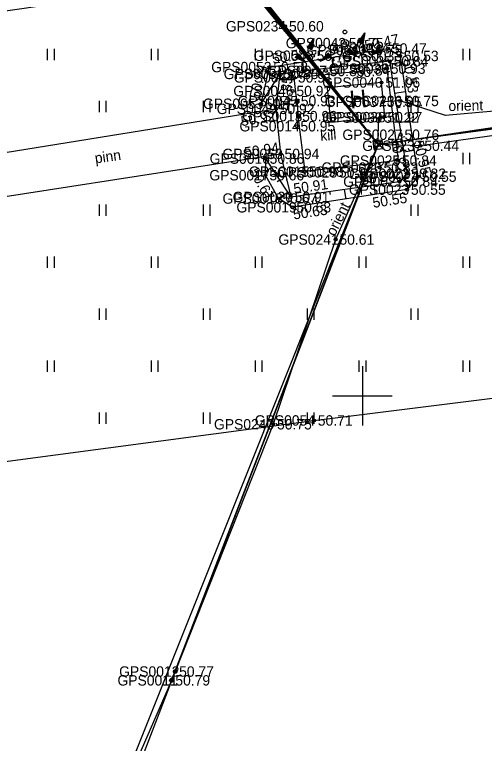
# Model space of a CAD drawing. Extents: x 563121 to 567545, y 6570841 to 6581299.
# Drawn here: x 565876.57 to 565908.23, y 6571676.57 to 6571725.69 of the extents above; entities that cross this region are included whole.
import ezdxf

# ---------------------------------------------------------------- set-up
doc = ezdxf.new("R2010")
doc.units = 0
for name, color, linetype in [('AED', 7, 'Continuous'), ('HALJASTUS', 7, 'Continuous'), ('HOONE', 7, 'Continuous'), ('KORGUS-EH2000', 7, 'Continuous'), ('MOOTKORG-EH2000', 7, 'Continuous'), ('MOOTMPUNKT', 7, 'Continuous'), ('MOOTNR', 7, 'Continuous'), ('MOOTPIIR', 7, 'Continuous'), ('MPKAABEL', 7, 'Continuous'), ('POST', 7, 'Continuous'), ('PUU', 7, 'Continuous'), ('RAJATIS', 7, 'Continuous'), ('RELJEEF', 7, 'Continuous'), ('SIOHULIIN', 7, 'Continuous'), ('TEE', 7, 'Continuous'), ('VORK', 7, 'Continuous')]:
    doc.layers.add(name, color=color, linetype=linetype)

msp = doc.modelspace()

# ---------------------------------------------------------------- linework, layer by layer
at = {"layer": 'AED'}
for p, q in [((565895.47, 6571719.988), (565895.47, 6571719.738)), ((565895.47, 6571719.988), (565895.72, 6571719.988)), ((565895.595, 6571719.863), (565895.684, 6571718.847)), ((565895.72, 6571719.988), (565895.72, 6571719.738)), ((565895.47, 6571719.738), (565895.72, 6571719.738)), ((565895.559, 6571718.972), (565895.559, 6571718.722)), ((565895.559, 6571718.972), (565895.809, 6571718.972)), ((565895.809, 6571718.972), (565895.809, 6571718.722)), ((565895.559, 6571718.722), (565895.809, 6571718.722))]:
    msp.add_line(p, q, dxfattribs=at)
msp.add_lwpolyline([(565895.595, 6571719.863), (565895.398, 6571721.461), (565901.655, 6571722.049), (565902.407, 6571715.849), (565896.139, 6571715.109), (565895.684, 6571718.847)], dxfattribs=at)
at = {"layer": 'HALJASTUS'}
for p, q in [((565878.772, 6571723.381), (565878.772, 6571722.619)), ((565879.228, 6571723.381), (565879.228, 6571722.619)), ((565885.772, 6571723.381), (565885.772, 6571722.619)), ((565886.228, 6571723.381), (565886.228, 6571722.619)), ((565892.772, 6571723.381), (565892.772, 6571722.619)), ((565893.228, 6571723.381), (565893.228, 6571722.619)), ((565906.772, 6571723.381), (565906.772, 6571722.619)), ((565907.228, 6571723.381), (565907.228, 6571722.619)), ((565882.272, 6571719.881), (565882.272, 6571719.119)), ((565882.728, 6571719.881), (565882.728, 6571719.119)), ((565889.272, 6571719.881), (565889.272, 6571719.119)), ((565889.728, 6571719.881), (565889.728, 6571719.119)), ((565903.272, 6571719.881), (565903.272, 6571719.119)), ((565903.728, 6571719.881), (565903.728, 6571719.119)), ((565906.772, 6571716.381), (565906.772, 6571715.619)), ((565907.228, 6571716.381), (565907.228, 6571715.619)), ((565882.272, 6571712.881), (565882.272, 6571712.119)), ((565882.728, 6571712.881), (565882.728, 6571712.119)), ((565889.272, 6571712.881), (565889.272, 6571712.119)), ((565889.728, 6571712.881), (565889.728, 6571712.119)), ((565903.272, 6571712.881), (565903.272, 6571712.119)), ((565903.728, 6571712.881), (565903.728, 6571712.119)), ((565878.772, 6571709.381), (565878.772, 6571708.619)), ((565879.228, 6571709.381), (565879.228, 6571708.619)), ((565885.772, 6571709.381), (565885.772, 6571708.619)), ((565886.228, 6571709.381), (565886.228, 6571708.619)), ((565892.772, 6571709.381), (565892.772, 6571708.619)), ((565893.228, 6571709.381), (565893.228, 6571708.619)), ((565899.772, 6571709.381), (565899.772, 6571708.619)), ((565900.228, 6571709.381), (565900.228, 6571708.619)), ((565906.772, 6571709.381), (565906.772, 6571708.619)), ((565907.228, 6571709.381), (565907.228, 6571708.619)), ((565882.272, 6571705.881), (565882.272, 6571705.119)), ((565882.728, 6571705.881), (565882.728, 6571705.119)), ((565889.272, 6571705.881), (565889.272, 6571705.119)), ((565889.728, 6571705.881), (565889.728, 6571705.119)), ((565896.272, 6571705.881), (565896.272, 6571705.119)), ((565896.728, 6571705.881), (565896.728, 6571705.119)), ((565903.272, 6571705.881), (565903.272, 6571705.119)), ((565903.728, 6571705.881), (565903.728, 6571705.119)), ((565878.772, 6571702.381), (565878.772, 6571701.619)), ((565879.228, 6571702.381), (565879.228, 6571701.619)), ((565885.772, 6571702.381), (565885.772, 6571701.619)), ((565886.228, 6571702.381), (565886.228, 6571701.619)), ((565892.772, 6571702.381), (565892.772, 6571701.619)), ((565893.228, 6571702.381), (565893.228, 6571701.619)), ((565899.772, 6571702.381), (565899.772, 6571701.619)), ((565900.228, 6571702.381), (565900.228, 6571701.619)), ((565906.772, 6571702.381), (565906.772, 6571701.619)), ((565907.228, 6571702.381), (565907.228, 6571701.619)), ((565882.272, 6571698.881), (565882.272, 6571698.119)), ((565882.728, 6571698.881), (565882.728, 6571698.119)), ((565889.272, 6571698.881), (565889.272, 6571698.119)), ((565889.728, 6571698.881), (565889.728, 6571698.119)), ((565896.272, 6571698.881), (565896.272, 6571698.119)), ((565896.728, 6571698.881), (565896.728, 6571698.119))]:
    msp.add_line(p, q, dxfattribs=at)
at = {"layer": 'KORGUS-EH2000'}
for centre in [(565901.738, 6571723.406), (565902.538, 6571722.902), (565901.848, 6571722.544), (565893.739, 6571722.155), (565894.437, 6571721.691), (565893.18, 6571719.681), (565894.174, 6571719.336), (565894.496, 6571716.301), (565903.034, 6571714.964), (565902.49, 6571714.435), (565903.744, 6571714.768), (565903.014, 6571713.894), (565895.181, 6571713.4), (565894.357, 6571713.294), (565895.296, 6571712.704), (565898.197, 6571710.531), (565896.74, 6571698.337)]:
    msp.add_circle(centre, 0.1, dxfattribs=at)
at = {"layer": 'MOOTMPUNKT'}
for centre in [(565894.796, 6571724.904), (565898.828, 6571723.769), (565900.099, 6571723.304), (565901.738, 6571723.406), (565896.666, 6571722.92), (565902.538, 6571722.902), (565901.848, 6571722.544), (565893.739, 6571722.155), (565894.437, 6571721.691), (565897.546, 6571721.893), (565901.655, 6571722.049), (565895.398, 6571721.461), (565901.292, 6571721.115), (565895.298, 6571720.541), (565895.595, 6571719.863), (565901.383, 6571719.81), (565902.551, 6571719.869), (565893.18, 6571719.681), (565894.174, 6571719.336), (565895.684, 6571718.847), (565901.218, 6571718.748), (565901.435, 6571718.779), (565895.569, 6571718.167), (565902.576, 6571717.595), (565903.915, 6571716.853), (565894.496, 6571716.301), (565893.493, 6571715.986), (565902.407, 6571715.849), (565901.169, 6571715.383), (565893.476, 6571714.867), (565896.139, 6571715.109), (565898.167, 6571715.059), (565903.034, 6571714.964), (565902.49, 6571714.435), (565903.744, 6571714.768), (565903.014, 6571713.894), (565895.181, 6571713.4), (565894.357, 6571713.294), (565895.296, 6571712.704), (565898.197, 6571710.531), (565896.74, 6571698.337), (565893.993, 6571698.08), (565887.395, 6571681.416), (565887.141, 6571680.821)]:
    msp.add_circle(centre, 0.1, dxfattribs=at)
at = {"layer": 'MOOTPIIR'}
msp.add_lwpolyline([(565847.666, 6571692.22), (565872.552, 6571695.122), (565896.74, 6571698.337), (565923.667, 6571701.7), (565921.225, 6571716.927), (565918.14, 6571731.716), (565901.33, 6571729.772), (565893.791, 6571728.537), (565867.263, 6571724.668), (565843.294, 6571721.486)], dxfattribs=at)
at = {"layer": 'MPKAABEL'}
for points in [[(565868.038, 6571758.236), (565867.453, 6571757.822), (565877.123, 6571746.517), (565877.646, 6571745.913), (565888.681, 6571732.586), (565894.796, 6571724.904), (565901.066, 6571716.93)], [(565953.537, 6571723.916), (565953.549, 6571724.752), (565939.474, 6571722.251), (565938.668, 6571722.15), (565916.898, 6571718.657), (565903.915, 6571716.853), (565901.066, 6571716.93)], [(565921.258, 6571720.287), (565905.596, 6571718.882), (565902.551, 6571719.869), (565901.417, 6571719.812)], [(565901.066, 6571716.93), (565898.197, 6571710.531), (565893.993, 6571698.08), (565887.395, 6571681.416), (565887.141, 6571680.821), (565881.237, 6571667.241), (565881.853, 6571666.983)]]:
    msp.add_lwpolyline(points, dxfattribs=at)
at = {"layer": 'POST'}
for p, q in [((565900.739, 6571717.2), (565901.336, 6571717.257)), ((565901.394, 6571716.66), (565900.739, 6571717.2)), ((565900.796, 6571716.603), (565900.739, 6571717.2)), ((565901.336, 6571717.257), (565900.796, 6571716.603)), ((565901.394, 6571716.66), (565901.336, 6571717.257)), ((565900.796, 6571716.603), (565901.394, 6571716.66))]:
    msp.add_line(p, q, dxfattribs=at)
for points in [[(565868.038, 6571758.236), (565901.066, 6571716.93), (565867.453, 6571757.822)], [(565877.123, 6571746.517), (565901.066, 6571716.93), (565877.646, 6571745.913)], [(565953.537, 6571723.916), (565901.066, 6571716.93), (565953.549, 6571724.752)], [(565939.474, 6571722.251), (565901.066, 6571716.93), (565938.668, 6571722.15)], [(565881.853, 6571666.983), (565901.066, 6571716.93), (565881.237, 6571667.241)], [(565887.141, 6571680.821), (565901.066, 6571716.93), (565887.395, 6571681.416)]]:
    msp.add_lwpolyline(points, dxfattribs=at)
for centre, radius in [((565887.395, 6571681.416), 0.125), ((565887.395, 6571681.416), 0.105), ((565887.395, 6571681.416), 0.0851), ((565887.395, 6571681.416), 0.0651), ((565887.395, 6571681.416), 0.0451), ((565887.395, 6571681.416), 0.0251), ((565887.395, 6571681.416), 0.00511), ((565887.141, 6571680.821), 0.125), ((565887.141, 6571680.821), 0.105), ((565887.141, 6571680.821), 0.0851), ((565887.141, 6571680.821), 0.0651), ((565887.141, 6571680.821), 0.0451), ((565887.141, 6571680.821), 0.0251), ((565887.141, 6571680.821), 0.00511)]:
    msp.add_circle(centre, radius, dxfattribs=at)
at = {"layer": 'PUU'}
for centre, radius in [((565898.828, 6571724.519), 0.125), ((565898.828, 6571723.769), 0.25), ((565898.178, 6571723.394), 0.125), ((565899.478, 6571723.394), 0.125)]:
    msp.add_circle(centre, radius, dxfattribs=at)
at = {"layer": 'RAJATIS'}
msp.add_lwpolyline([(565901.292, 6571721.115), (565897.637, 6571720.765), (565897.859, 6571718.445), (565901.514, 6571718.795)], close=True, dxfattribs=at)
at = {"layer": 'RELJEEF'}
for p, q in [((565899.744, 6571723.83), (565900.164, 6571724.47)), ((565899.994, 6571724.205), (565900.124, 6571724.265)), ((565900.164, 6571724.47), (565900.024, 6571723.715)), ((565900.039, 6571724.28), (565900.139, 6571724.32)), ((565900.089, 6571724.355), (565900.149, 6571724.38)), ((565900.139, 6571724.43), (565900.159, 6571724.44)), ((565896.311, 6571723.446), (565896.731, 6571724.086)), ((565896.511, 6571723.746), (565896.681, 6571723.821)), ((565896.561, 6571723.821), (565896.691, 6571723.881)), ((565896.586, 6571723.726), (565896.671, 6571723.761)), ((565896.731, 6571724.086), (565896.591, 6571723.331)), ((565896.606, 6571723.896), (565896.706, 6571723.936)), ((565896.656, 6571723.971), (565896.716, 6571723.996)), ((565896.706, 6571724.046), (565896.726, 6571724.056)), ((565899.744, 6571723.83), (565900.069, 6571723.97)), ((565899.744, 6571723.83), (565900.024, 6571723.715)), ((565899.744, 6571723.83), (565899.744, 6571723.83)), ((565899.794, 6571723.905), (565900.079, 6571724.025)), ((565899.809, 6571723.805), (565900.059, 6571723.91)), ((565899.844, 6571723.98), (565900.094, 6571724.085)), ((565899.874, 6571723.775), (565900.049, 6571723.85)), ((565899.894, 6571724.055), (565900.019, 6571724.11)), ((565899.944, 6571724.13), (565900.114, 6571724.205)), ((565899.944, 6571723.75), (565900.039, 6571723.79)), ((565900.019, 6571724.11), (565900.104, 6571724.145)), ((565896.311, 6571723.446), (565896.636, 6571723.586)), ((565896.311, 6571723.446), (565896.591, 6571723.331)), ((565896.311, 6571723.446), (565896.311, 6571723.446)), ((565896.361, 6571723.521), (565896.646, 6571723.641)), ((565896.376, 6571723.421), (565896.626, 6571723.526)), ((565896.411, 6571723.596), (565896.661, 6571723.701)), ((565896.441, 6571723.391), (565896.616, 6571723.466)), ((565896.461, 6571723.671), (565896.586, 6571723.726)), ((565896.511, 6571723.366), (565896.606, 6571723.406)), ((565896.576, 6571723.341), (565896.591, 6571723.346)), ((565899.103, 6571723.429), (565898.918, 6571723.189)), ((565898.973, 6571723.259), (565898.988, 6571723.159)), ((565899.018, 6571723.319), (565899.043, 6571723.134)), ((565899.058, 6571723.374), (565899.093, 6571723.104)), ((565899.103, 6571723.429), (565899.608, 6571722.859)), ((565899.103, 6571723.429), (565899.148, 6571723.079)), ((565899.103, 6571723.429), (565899.103, 6571723.429)), ((565899.163, 6571723.364), (565899.203, 6571723.054)), ((565899.223, 6571723.294), (565899.258, 6571723.029)), ((565900.009, 6571723.725), (565900.024, 6571723.73)), ((565900.582, 6571722.924), (565901.122, 6571723.469)), ((565901.207, 6571723.184), (565900.902, 6571723.244)), ((565901.292, 6571723.219), (565900.942, 6571723.284)), ((565901.252, 6571723.274), (565900.987, 6571723.329)), ((565901.212, 6571723.334), (565901.027, 6571723.369)), ((565901.172, 6571723.394), (565901.072, 6571723.414)), ((565901.132, 6571723.454), (565901.112, 6571723.454)), ((565901.292, 6571723.219), (565901.122, 6571723.469)), ((565895.669, 6571723.045), (565895.484, 6571722.805)), ((565896.174, 6571722.475), (565895.484, 6571722.805)), ((565895.494, 6571722.82), (565895.499, 6571722.8)), ((565895.539, 6571722.875), (565895.554, 6571722.775)), ((565895.584, 6571722.935), (565895.609, 6571722.75)), ((565895.624, 6571722.99), (565895.659, 6571722.72)), ((565895.669, 6571723.045), (565896.174, 6571722.475)), ((565895.669, 6571723.045), (565895.714, 6571722.695)), ((565895.669, 6571723.045), (565895.669, 6571723.045)), ((565895.729, 6571722.98), (565895.769, 6571722.67)), ((565895.789, 6571722.91), (565895.824, 6571722.645)), ((565895.849, 6571722.845), (565895.864, 6571722.705)), ((565895.904, 6571722.775), (565895.934, 6571722.59)), ((565897.149, 6571722.54), (565897.689, 6571723.085)), ((565897.859, 6571722.835), (565897.149, 6571722.54)), ((565897.474, 6571722.755), (565897.384, 6571722.775)), ((565897.689, 6571722.765), (565897.424, 6571722.815)), ((565897.774, 6571722.8), (565897.469, 6571722.86)), ((565897.609, 6571722.73), (565897.474, 6571722.755)), ((565897.859, 6571722.835), (565897.509, 6571722.9)), ((565897.819, 6571722.89), (565897.554, 6571722.945)), ((565897.779, 6571722.95), (565897.594, 6571722.985)), ((565897.739, 6571723.01), (565897.639, 6571723.03)), ((565897.699, 6571723.07), (565897.679, 6571723.07)), ((565897.859, 6571722.835), (565897.689, 6571723.085)), ((565897.859, 6571722.835), (565897.859, 6571722.835)), ((565898.043, 6571722.106), (565897.961, 6571722.815)), ((565899.608, 6571722.859), (565898.918, 6571723.189)), ((565898.928, 6571723.204), (565898.933, 6571723.184)), ((565899.283, 6571723.229), (565899.298, 6571723.089)), ((565899.298, 6571723.089), (565899.313, 6571722.999)), ((565899.338, 6571723.159), (565899.368, 6571722.974)), ((565899.398, 6571723.094), (565899.418, 6571722.949)), ((565899.458, 6571723.024), (565899.473, 6571722.924)), ((565899.518, 6571722.959), (565899.528, 6571722.894)), ((565899.578, 6571722.889), (565899.583, 6571722.869)), ((565900.03, 6571722.334), (565899.939, 6571723.124)), ((565901.292, 6571723.219), (565900.582, 6571722.924)), ((565900.622, 6571722.939), (565900.607, 6571722.944)), ((565900.707, 6571722.974), (565900.647, 6571722.989)), ((565900.792, 6571723.009), (565900.687, 6571723.029)), ((565900.872, 6571723.044), (565900.732, 6571723.074)), ((565900.957, 6571723.079), (565900.772, 6571723.114)), ((565900.907, 6571723.139), (565900.817, 6571723.159)), ((565901.122, 6571723.149), (565900.857, 6571723.199)), ((565901.042, 6571723.114), (565900.907, 6571723.139)), ((565901.292, 6571723.219), (565901.292, 6571723.219)), ((565895.864, 6571722.705), (565895.879, 6571722.615)), ((565895.964, 6571722.71), (565895.984, 6571722.565)), ((565896.056, 6571721.877), (565895.984, 6571722.506)), ((565896.024, 6571722.64), (565896.039, 6571722.54)), ((565896.084, 6571722.575), (565896.094, 6571722.51)), ((565896.144, 6571722.505), (565896.149, 6571722.485)), ((565897.189, 6571722.555), (565897.174, 6571722.56)), ((565897.274, 6571722.59), (565897.214, 6571722.605)), ((565897.359, 6571722.625), (565897.254, 6571722.645)), ((565897.439, 6571722.66), (565897.299, 6571722.69)), ((565897.524, 6571722.695), (565897.339, 6571722.73)), ((565899.036, 6571722.22), (565899.011, 6571722.445)), ((565901.023, 6571722.449), (565900.995, 6571722.698)), ((565901.874, 6571722.376), (565902.599, 6571722.489)), ((565895.063, 6571721.763), (565895.042, 6571721.939)), ((565897.05, 6571721.991), (565897.027, 6571722.192)), ((565894.241, 6571721.377), (565893.647, 6571721.748)), ((565902.029, 6571721.388), (565902.244, 6571721.421)), ((565893.711, 6571720.529), (565893.622, 6571720.585)), ((565902.183, 6571720.4), (565902.892, 6571720.511)), ((565902.338, 6571719.412), (565902.548, 6571719.445)), ((565902.492, 6571718.424), (565903.186, 6571718.532)), ((565902.647, 6571717.436), (565902.853, 6571717.468)), ((565902.802, 6571716.448), (565903.479, 6571716.554)), ((565902.956, 6571715.46), (565903.157, 6571715.491)), ((565893.892, 6571715.375), (565893.48, 6571715.105)), ((565894.439, 6571714.537), (565894.268, 6571714.426)), ((565902.677, 6571714.617), (565903.183, 6571714.096)), ((565898.787, 6571713.911), (565898.88, 6571713.257)), ((565899.778, 6571714.051), (565899.805, 6571713.858)), ((565900.768, 6571714.191), (565900.857, 6571713.562)), ((565901.758, 6571714.331), (565901.784, 6571714.146)), ((565894.986, 6571713.7), (565894.361, 6571713.292)), ((565895.817, 6571713.49), (565895.846, 6571713.283)), ((565896.807, 6571713.63), (565896.903, 6571712.952)), ((565897.797, 6571713.77), (565897.826, 6571713.571))]:
    msp.add_line(p, q, dxfattribs=at)
for points in [[(565893.18, 6571719.681), (565893.739, 6571722.155), (565901.738, 6571723.406), (565902.538, 6571722.902), (565903.744, 6571714.768), (565903.014, 6571713.894), (565895.296, 6571712.704), (565894.357, 6571713.294), (565893.476, 6571714.867), (565893.493, 6571715.986)], [(565893.18, 6571719.681), (565894.437, 6571721.691)], [(565895.181, 6571713.4), (565893.493, 6571715.986)]]:
    msp.add_lwpolyline(points, dxfattribs=at)
at = {"layer": 'SIOHULIIN'}
msp.add_line((565901.066, 6571716.93), (565901.087, 6571718.754), dxfattribs=at)
at = {"layer": 'TEE'}
for points in [[(565894.437, 6571721.691), (565894.174, 6571719.336), (565894.496, 6571716.301), (565895.181, 6571713.4), (565902.49, 6571714.435), (565903.034, 6571714.964), (565901.848, 6571722.544), (565894.437, 6571721.691)], [(565820.53, 6571709.209), (565844.801, 6571711.57), (565868.944, 6571715.283), (565894.174, 6571719.336)], [(565821.038, 6571705.752), (565845.152, 6571708.73), (565869.253, 6571712.407), (565894.496, 6571716.301)]]:
    msp.add_lwpolyline(points, dxfattribs=at)
at = {"layer": 'VORK'}
for p, q in [((565900, 6571702), (565900, 6571698)), ((565898, 6571700), (565902, 6571700))]:
    msp.add_line(p, q, dxfattribs=at)

# ---------------------------------------------------------------- texts
at = {"layer": 'HOONE'}
msp.add_text('H', height=1.2, rotation=5.47, dxfattribs=at).set_placement((565899.193, 6571719.349))
at = {"layer": 'KORGUS-EH2000'}
for s, rotation, p in [(' 50.47', 11.2374, (565899.97, 6571723.205)), (' 50.58', 8.8898, (565893.712, 6571722.327)), (' 50.74', 77.2742, (565893.01, 6571719.72)), (' 50.84', 6.564, (565899.322, 6571721.367)), (' 50.53', 278.4387, (565902.711, 6571722.928)), (' 50.85', 83.6224, (565895.012, 6571718.912)), (' 50.92', 9.1256, (565891.618, 6571718.123)), (' 50.82', 278.8915, (565901.881, 6571717.572)), (' 50.94', 8.7691, (565891.854, 6571716.006)), (' 50.55', 283.5343, (565903.37, 6571717.359)), (' 50.67', 299.2515, (565892.243, 6571715.334)), (' 50.84', 8.9315, (565899.721, 6571714.172)), (' 50.91', 8.0569, (565895.157, 6571713.573)), (' 50.55', 8.7716, (565900.49, 6571712.621)), (' 50.63', 8.3966, (565895.125, 6571711.839))]:
    msp.add_text(s, height=0.7, rotation=rotation, dxfattribs=at).set_placement(p)
for s, p in [(' 50.61', (565898.197, 6571710.181)), (' 50.71', (565896.74, 6571697.987))]:
    msp.add_text(s, height=0.7, dxfattribs=at).set_placement(p)
at = {"layer": 'MOOTKORG-EH2000'}
for s, p in [(' 50.60', (565894.796, 6571724.554)), (' 50.75', (565898.828, 6571723.419)), (' 50.47', (565901.738, 6571723.056)), (' 50.74', (565896.666, 6571722.57)), (' 50.75', (565900.099, 6571722.954)), (' 50.53', (565902.538, 6571722.552)), (' 50.84', (565901.848, 6571722.194)), (' 50.58', (565893.739, 6571721.805)), (' 50.93', (565901.655, 6571721.699)), (' 50.85', (565894.437, 6571721.341)), (' 50.91', (565895.398, 6571721.111)), (' 50.88', (565897.546, 6571721.543)), (' 51.06', (565901.292, 6571720.765)), (' 50.92', (565895.298, 6571720.191)), (' 50.74', (565893.18, 6571719.331)), (' 50.93', (565895.595, 6571719.514)), (' 50.95', (565901.383, 6571719.46)), (' 50.75', (565902.551, 6571719.519)), (' 50.92', (565894.174, 6571718.986)), (' 50.96', (565895.684, 6571718.497)), (' 51.22', (565901.218, 6571718.398)), (' 50.97', (565901.435, 6571718.429)), (' 50.95', (565895.569, 6571717.817)), (' 50.76', (565902.576, 6571717.245)), (' 50.44', (565903.915, 6571716.503)), (' 50.94', (565894.496, 6571715.951)), (' 50.86', (565893.493, 6571715.636)), (' 50.84', (565902.407, 6571715.499)), (' 50.98', (565896.139, 6571714.759)), (' 50.96', (565898.167, 6571714.709)), (' 50.83', (565901.169, 6571715.033)), (' 50.66', (565893.476, 6571714.517)), (' 50.82', (565903.034, 6571714.614)), (' 50.55', (565903.744, 6571714.418)), (' 50.84', (565902.49, 6571714.085)), (' 50.55', (565903.014, 6571713.544)), (' 50.67', (565894.357, 6571712.944)), (' 50.91', (565895.181, 6571713.05)), (' 50.63', (565895.296, 6571712.354)), (' 50.61', (565898.197, 6571710.181)), (' 50.71', (565896.74, 6571697.987)), (' 50.75', (565893.993, 6571697.73)), (' 50.77', (565887.395, 6571681.066)), (' 50.79', (565887.141, 6571680.471))]:
    msp.add_text(s, height=0.7, dxfattribs=at).set_placement(p)
at = {"layer": 'MOOTNR'}
for s, p in [('GPS0234 ', (565890.806, 6571724.554)), ('GPS0042 ', (565894.839, 6571723.419)), ('GPS0034 ', (565897.748, 6571723.056)), ('GPS0043 ', (565892.676, 6571722.57)), ('GPS0041 ', (565896.249, 6571722.954)), ('GPS0033 ', (565898.618, 6571722.552)), ('GPS0035 ', (565897.928, 6571722.194)), ('GPS0052 ', (565889.819, 6571721.805)), ('GPS0036 ', (565897.735, 6571721.699)), ('GPS0051 ', (565890.658, 6571721.341)), ('GPS0044 ', (565891.338, 6571721.111)), ('GPS0047 ', (565893.556, 6571721.543)), ('GPS0040 ', (565897.302, 6571720.765)), ('GPS0046 ', (565891.308, 6571720.191)), ('GPS0053 ', (565889.261, 6571719.331)), ('GPS0045 ', (565891.605, 6571719.514)), ('GPS0037 ', (565897.463, 6571719.46)), ('GPS0236 ', (565898.631, 6571719.519)), ('GPS0049 ', (565890.184, 6571718.986)), ('GPS0013 ', (565891.904, 6571718.497)), ('GPS0039 ', (565897.299, 6571718.398)), ('GPS0038 ', (565897.515, 6571718.429)), ('GPS0014 ', (565891.719, 6571717.817)), ('GPS0027 ', (565898.657, 6571717.245)), ('GPS0237 ', (565899.995, 6571716.503)), ('GPS0050 ', (565890.576, 6571715.951)), ('GPS0016 ', (565889.713, 6571715.636)), ('GPS0025 ', (565898.487, 6571715.499)), ('GPS0015 ', (565892.359, 6571714.759)), ('GPS0028 ', (565894.247, 6571714.709)), ('GPS0026 ', (565897.249, 6571715.033)), ('GPS0017 ', (565889.696, 6571714.517)), ('GPS0022 ', (565899.114, 6571714.614)), ('GPS0024 ', (565899.755, 6571714.418)), ('GPS0021 ', (565898.71, 6571714.085)), ('GPS0023 ', (565899.094, 6571713.544)), ('GPS0018 ', (565890.578, 6571712.944)), ('GPS0020 ', (565891.262, 6571713.05)), ('GPS0019 ', (565891.516, 6571712.354)), ('GPS0241 ', (565894.347, 6571710.181)), ('GPS0054 ', (565892.751, 6571697.987)), ('GPS0240 ', (565890.004, 6571697.73)), ('GPS0012 ', (565883.615, 6571681.066)), ('GPS0011 ', (565883.501, 6571680.471))]:
    msp.add_text(s, height=0.7, dxfattribs=at).set_placement(p)
at = {"layer": 'MPKAABEL'}
for rotation, p in [(1.2361, (565905.807, 6571719.186)), (63.6112, (565898.138, 6571710.718))]:
    msp.add_text('orient', height=0.7, rotation=rotation, dxfattribs=at).set_placement(p)
at = {"layer": 'TEE'}
for s, rotation, p in [('kill', 4.6314, (565897.189, 6571717.173)), ('pinn', 8.0456, (565882.022, 6571715.659))]:
    msp.add_text(s, height=0.7, rotation=rotation, dxfattribs=at).set_placement(p)

doc.saveas('drawing.dxf')
